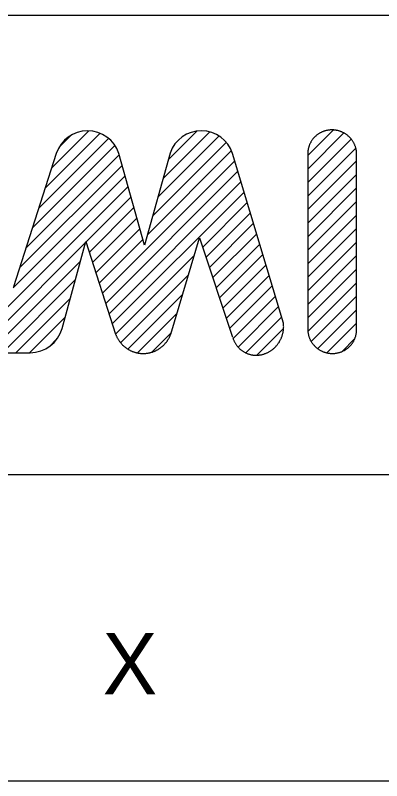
# Model space of a CAD drawing. Extents: x 563 to 1404, y 358 to 952.
# Drawn here: x 1199.82 to 1211.79, y 387.96 to 412.96 of the extents above; entities that cross this region are included whole.
import ezdxf

# ---------------------------------------------------------------- set-up
doc = ezdxf.new("R2010")
doc.units = 0
doc.layers.add('New Level (0)', color=7, linetype='Continuous')

# ---------------------------------------------------------------- blocks, each defined once
blk = doc.blocks.new('_U2')
at = {"layer": 'New Level (0)'}
for p, q in [((-3.034, 1.765), (-1.24, 3.56)), ((-2.825, 2.416), (-1.602, 3.64)), ((0.817, 2.081), (2.342, 3.605)), ((0.987, 2.693), (1.925, 3.631)), ((5.546, 2.833), (6.381, 3.668)), ((5.546, 2.391), (6.725, 3.57)), ((5.849, 3.507), (5.834, 3.495)), ((5.865, 3.518), (5.849, 3.507)), ((5.88, 3.529), (5.865, 3.518)), ((5.896, 3.54), (5.88, 3.529)), ((5.913, 3.55), (5.896, 3.54)), ((5.929, 3.56), (5.913, 3.55)), ((5.946, 3.57), (5.929, 3.56)), ((5.963, 3.579), (5.946, 3.57)), ((5.98, 3.587), (5.963, 3.579)), ((5.997, 3.596), (5.98, 3.587)), ((6.015, 3.603), (5.997, 3.596)), ((6.033, 3.611), (6.015, 3.603)), ((6.051, 3.618), (6.033, 3.611)), ((6.069, 3.624), (6.051, 3.618)), ((6.087, 3.631), (6.069, 3.624)), ((6.105, 3.636), (6.087, 3.631)), ((6.124, 3.642), (6.105, 3.636)), ((6.143, 3.646), (6.124, 3.642)), ((6.162, 3.651), (6.143, 3.646)), ((6.181, 3.655), (6.162, 3.651)), ((6.2, 3.658), (6.181, 3.655)), ((6.219, 3.661), (6.2, 3.658)), ((6.238, 3.664), (6.219, 3.661)), ((6.257, 3.666), (6.238, 3.664)), ((6.277, 3.667), (6.257, 3.666)), ((6.296, 3.668), (6.277, 3.667)), ((6.315, 3.669), (6.296, 3.668)), ((6.335, 3.669), (6.315, 3.669)), ((6.354, 3.669), (6.335, 3.669)), ((6.373, 3.668), (6.354, 3.669)), ((6.393, 3.667), (6.373, 3.668)), ((6.412, 3.666), (6.393, 3.667)), ((6.432, 3.664), (6.412, 3.666)), ((6.451, 3.661), (6.432, 3.664)), ((6.47, 3.658), (6.451, 3.661)), ((6.489, 3.655), (6.47, 3.658)), ((6.508, 3.651), (6.489, 3.655)), ((6.527, 3.646), (6.508, 3.651)), ((6.546, 3.641), (6.527, 3.646)), ((6.565, 3.636), (6.546, 3.641)), ((6.583, 3.631), (6.565, 3.636)), ((6.602, 3.624), (6.583, 3.631)), ((6.62, 3.618), (6.602, 3.624)), ((6.638, 3.611), (6.62, 3.618)), ((6.656, 3.603), (6.638, 3.611)), ((6.674, 3.596), (6.656, 3.603)), ((6.691, 3.587), (6.674, 3.596)), ((6.709, 3.579), (6.691, 3.587)), ((6.726, 3.57), (6.709, 3.579)), ((6.743, 3.56), (6.726, 3.57)), ((6.759, 3.55), (6.743, 3.56)), ((6.776, 3.54), (6.759, 3.55)), ((6.792, 3.529), (6.776, 3.54)), ((6.808, 3.518), (6.792, 3.529)), ((6.823, 3.507), (6.808, 3.518)), ((6.839, 3.495), (6.823, 3.507)), ((-3.244, 1.114), (-0.964, 3.394)), ((-2.578, 3.105), (-2.187, 3.496)), ((0.476, 0.856), (2.885, 3.265)), ((0.647, 1.468), (2.649, 3.471)), ((5.546, 1.949), (6.967, 3.369)), ((5.64, 3.263), (5.631, 3.246)), ((5.649, 3.28), (5.64, 3.263)), ((5.659, 3.296), (5.649, 3.28)), ((5.669, 3.312), (5.659, 3.296)), ((5.679, 3.328), (5.669, 3.312)), ((5.69, 3.343), (5.679, 3.328)), ((5.701, 3.359), (5.69, 3.343)), ((5.713, 3.374), (5.701, 3.359)), ((5.725, 3.389), (5.713, 3.374)), ((5.738, 3.403), (5.725, 3.389)), ((5.75, 3.417), (5.738, 3.403)), ((5.764, 3.431), (5.75, 3.417)), ((5.777, 3.444), (5.764, 3.431)), ((5.791, 3.458), (5.777, 3.444)), ((5.805, 3.47), (5.791, 3.458)), ((5.82, 3.483), (5.805, 3.47)), ((5.834, 3.495), (5.82, 3.483)), ((6.854, 3.483), (6.839, 3.495)), ((6.869, 3.47), (6.854, 3.483)), ((6.883, 3.457), (6.869, 3.47)), ((6.897, 3.444), (6.883, 3.457)), ((6.911, 3.431), (6.897, 3.444)), ((6.924, 3.417), (6.911, 3.431)), ((6.938, 3.403), (6.924, 3.417)), ((6.95, 3.388), (6.938, 3.403)), ((6.963, 3.374), (6.95, 3.388)), ((6.975, 3.359), (6.963, 3.374)), ((6.986, 3.343), (6.975, 3.359)), ((6.998, 3.328), (6.986, 3.343)), ((7.009, 3.312), (6.998, 3.328)), ((7.019, 3.296), (7.009, 3.312)), ((7.029, 3.28), (7.019, 3.296)), ((7.039, 3.263), (7.029, 3.28)), ((7.048, 3.246), (7.039, 3.263)), ((-3.453, 0.463), (-0.754, 3.161)), ((5.546, 1.507), (7.115, 3.076)), ((5.555, 3.013), (5.552, 2.994)), ((5.558, 3.032), (5.555, 3.013)), ((5.562, 3.05), (5.558, 3.032)), ((5.566, 3.069), (5.562, 3.05)), ((5.57, 3.087), (5.566, 3.069)), ((5.575, 3.105), (5.57, 3.087)), ((5.58, 3.124), (5.575, 3.105)), ((5.586, 3.142), (5.58, 3.124)), ((5.593, 3.159), (5.586, 3.142)), ((5.599, 3.177), (5.593, 3.159)), ((5.606, 3.195), (5.599, 3.177)), ((5.614, 3.212), (5.606, 3.195)), ((5.622, 3.229), (5.614, 3.212)), ((5.631, 3.246), (5.622, 3.229)), ((7.057, 3.229), (7.048, 3.246)), ((7.065, 3.212), (7.057, 3.229)), ((7.073, 3.195), (7.065, 3.212)), ((7.081, 3.177), (7.073, 3.195)), ((7.088, 3.159), (7.081, 3.177)), ((7.095, 3.141), (7.088, 3.159)), ((7.101, 3.123), (7.095, 3.141)), ((7.107, 3.105), (7.101, 3.123)), ((7.112, 3.087), (7.107, 3.105)), ((7.117, 3.069), (7.112, 3.087)), ((7.121, 3.05), (7.117, 3.069)), ((7.125, 3.031), (7.121, 3.05)), ((7.129, 3.013), (7.125, 3.031)), ((7.132, 2.994), (7.129, 3.013)), ((-2.669, 2.903), (-4.069, -1.454)), ((-3.662, -0.189), (-0.616, 2.857)), ((0.211, -0.097), (-0.629, 2.903)), ((1.048, 2.913), (0.211, -0.097)), ((0.306, 0.244), (3.056, 2.994)), ((4.75, -2.642), (3.091, 2.903)), ((5.547, 2.937), (5.546, 2.918)), ((5.546, 2.918), (5.546, 2.899)), ((5.546, 2.899), (5.546, 2.88)), ((5.546, 2.876), (5.546, -2.887)), ((5.548, 2.956), (5.547, 2.937)), ((5.55, 2.975), (5.548, 2.956)), ((5.552, 2.994), (5.55, 2.975)), ((7.135, 2.975), (7.132, 2.994)), ((7.137, 2.956), (7.135, 2.975)), ((7.138, 2.937), (7.137, 2.956)), ((7.139, 2.918), (7.138, 2.937)), ((7.139, -2.841), (7.139, 2.923)), ((-3.871, -0.84), (-0.52, 2.512)), ((-1.163, -1.667), (3.164, 2.66)), ((5.546, 1.065), (7.139, 2.658)), ((-1.056, -2.001), (3.266, 2.32)), ((-4.081, -1.492), (-0.423, 2.167)), ((5.546, 0.623), (7.139, 2.216)), ((-5.755, -3.607), (-0.326, 1.822)), ((-0.948, -2.336), (3.367, 1.98)), ((5.546, 0.181), (7.139, 1.774)), ((-0.84, -2.67), (3.469, 1.639)), ((-1.703, 0.003), (-0.23, 1.476)), ((2.112, -0.16), (3.571, 1.299)), ((5.546, -0.261), (7.139, 1.332)), ((-1.595, -0.331), (-0.133, 1.131)), ((-1.487, -0.665), (-0.036, 0.786)), ((2.222, -0.491), (3.673, 0.959)), ((5.546, -0.703), (7.139, 0.89)), ((2.333, -0.823), (3.774, 0.619)), ((-1.379, -0.999), (0.06, 0.44)), ((2.443, -1.154), (3.876, 0.279)), ((5.546, -1.145), (7.139, 0.448)), ((-2.482, -2.818), (-1.709, 0.023)), ((-1.709, 0.023), (-0.734, -2.997)), ((-1.271, -1.333), (0.157, 0.095)), ((1.072, -2.999), (2.011, 0.143)), ((2.011, 0.143), (3.091, -3.097)), ((5.546, -1.587), (7.139, 0.006)), ((-5.313, -3.607), (-1.719, -0.013)), ((2.554, -1.486), (3.978, -0.061)), ((-0.732, -3.004), (1.839, -0.433)), ((2.664, -1.817), (4.08, -0.402)), ((5.546, -2.028), (7.139, -0.436)), ((-4.871, -3.607), (-1.884, -0.62)), ((2.775, -2.149), (4.182, -0.742)), ((5.546, -2.47), (7.139, -0.878)), ((-4.429, -3.607), (-2.049, -1.227)), ((-0.569, -3.283), (1.651, -1.063)), ((2.885, -2.48), (4.283, -1.082)), ((2.996, -2.811), (4.385, -1.422)), ((5.548, -2.911), (7.139, -1.32)), ((-0.334, -3.49), (1.462, -1.694)), ((-3.987, -3.607), (-2.215, -1.835)), ((3.106, -3.143), (4.487, -1.762)), ((5.657, -3.243), (7.139, -1.762)), ((3.268, -3.423), (4.589, -2.102)), ((5.869, -3.474), (7.139, -2.204)), ((-3.545, -3.607), (-2.38, -2.442)), ((-0.018, -3.615), (1.273, -2.324)), ((3.52, -3.613), (4.691, -2.442)), ((4.749, -2.635), (4.746, -2.615)), ((4.752, -2.655), (4.749, -2.635)), ((4.754, -2.676), (4.752, -2.655)), ((4.756, -2.696), (4.754, -2.676)), ((4.757, -2.717), (4.756, -2.696)), ((4.757, -2.737), (4.757, -2.717)), ((4.758, -2.758), (4.757, -2.737)), ((6.172, -3.612), (7.139, -2.646)), ((0.447, -3.592), (1.085, -2.954)), ((3.886, -3.689), (4.755, -2.82)), ((4.724, -3.004), (4.73, -2.984)), ((4.73, -2.984), (4.734, -2.964)), ((4.734, -2.964), (4.739, -2.943)), ((4.739, -2.943), (4.743, -2.923)), ((4.743, -2.923), (4.746, -2.902)), ((4.746, -2.902), (4.749, -2.882)), ((4.749, -2.882), (4.752, -2.861)), ((4.752, -2.861), (4.754, -2.841)), ((4.754, -2.841), (4.755, -2.82)), ((4.755, -2.82), (4.757, -2.799)), ((4.757, -2.779), (4.758, -2.758)), ((4.757, -2.799), (4.757, -2.779)), ((5.546, -2.882), (5.547, -2.901)), ((5.547, -2.901), (5.549, -2.92)), ((5.549, -2.92), (5.551, -2.939)), ((5.551, -2.939), (5.554, -2.958)), ((5.554, -2.958), (5.557, -2.976)), ((5.557, -2.976), (5.56, -2.995)), ((5.56, -2.995), (5.564, -3.014)), ((7.124, -3.013), (7.128, -2.994)), ((7.128, -2.994), (7.131, -2.976)), ((7.131, -2.976), (7.133, -2.957)), ((7.133, -2.957), (7.136, -2.938)), ((7.136, -2.938), (7.137, -2.919)), ((7.137, -2.919), (7.138, -2.9)), ((7.138, -2.9), (7.139, -2.881)), ((7.139, -2.862), (7.139, -2.843)), ((7.139, -2.881), (7.139, -2.862)), ((-2.919, -3.423), (-2.627, -3.131)), ((-0.732, -3.003), (-0.725, -3.021)), ((-0.725, -3.021), (-0.718, -3.038)), ((-0.718, -3.038), (-0.711, -3.055)), ((-0.711, -3.055), (-0.703, -3.071)), ((-0.703, -3.071), (-0.695, -3.088)), ((-0.695, -3.088), (-0.687, -3.104)), ((-0.687, -3.104), (-0.678, -3.121)), ((-0.678, -3.121), (-0.67, -3.137)), ((-0.67, -3.137), (-0.66, -3.153)), ((-0.66, -3.153), (-0.651, -3.169)), ((-0.651, -3.169), (-0.641, -3.184)), ((-0.641, -3.184), (-0.631, -3.2)), ((-0.631, -3.2), (-0.621, -3.215)), ((-0.621, -3.215), (-0.61, -3.23)), ((-0.61, -3.23), (-0.6, -3.245)), ((-0.6, -3.245), (-0.588, -3.259)), ((0.925, -3.261), (0.937, -3.247)), ((0.937, -3.247), (0.947, -3.232)), ((0.947, -3.232), (0.958, -3.217)), ((0.958, -3.217), (0.968, -3.202)), ((0.968, -3.202), (0.978, -3.186)), ((0.978, -3.186), (0.988, -3.171)), ((0.988, -3.171), (0.998, -3.155)), ((0.998, -3.155), (1.007, -3.139)), ((1.007, -3.139), (1.016, -3.123)), ((1.016, -3.123), (1.024, -3.106)), ((1.024, -3.106), (1.032, -3.09)), ((1.032, -3.09), (1.04, -3.073)), ((1.04, -3.073), (1.048, -3.057)), ((1.048, -3.057), (1.055, -3.04)), ((1.055, -3.04), (1.063, -3.023)), ((1.063, -3.023), (1.069, -3.005)), ((3.1, -3.125), (3.106, -3.144)), ((3.106, -3.144), (3.113, -3.163)), ((3.113, -3.163), (3.12, -3.182)), ((3.12, -3.182), (3.128, -3.201)), ((3.128, -3.201), (3.136, -3.219)), ((3.136, -3.219), (3.145, -3.237)), ((3.145, -3.237), (3.154, -3.255)), ((4.617, -3.253), (4.627, -3.235)), ((4.627, -3.235), (4.638, -3.217)), ((4.638, -3.217), (4.648, -3.198)), ((4.648, -3.198), (4.657, -3.18)), ((4.657, -3.18), (4.666, -3.161)), ((4.666, -3.161), (4.675, -3.142)), ((4.675, -3.142), (4.683, -3.123)), ((4.683, -3.123), (4.691, -3.103)), ((4.691, -3.103), (4.699, -3.084)), ((4.699, -3.084), (4.706, -3.064)), ((4.706, -3.064), (4.712, -3.044)), ((4.712, -3.044), (4.719, -3.024)), ((4.719, -3.024), (4.724, -3.004)), ((5.564, -3.014), (5.569, -3.032)), ((5.569, -3.032), (5.574, -3.051)), ((5.574, -3.051), (5.579, -3.069)), ((5.579, -3.069), (5.585, -3.087)), ((5.585, -3.087), (5.591, -3.105)), ((5.591, -3.105), (5.598, -3.123)), ((5.598, -3.123), (5.605, -3.141)), ((5.605, -3.141), (5.613, -3.158)), ((5.613, -3.158), (5.621, -3.176)), ((5.621, -3.176), (5.629, -3.193)), ((5.629, -3.193), (5.638, -3.21)), ((5.638, -3.21), (5.647, -3.227)), ((5.647, -3.227), (5.657, -3.243)), ((5.657, -3.243), (5.667, -3.259)), ((6.653, -3.574), (7.086, -3.141)), ((7.027, -3.259), (7.037, -3.242)), ((7.037, -3.242), (7.046, -3.226)), ((7.046, -3.226), (7.055, -3.209)), ((7.055, -3.209), (7.064, -3.192)), ((7.064, -3.192), (7.072, -3.175)), ((7.072, -3.175), (7.079, -3.158)), ((7.079, -3.158), (7.086, -3.14)), ((7.086, -3.14), (7.093, -3.122)), ((7.093, -3.122), (7.099, -3.104)), ((7.099, -3.104), (7.105, -3.086)), ((7.105, -3.086), (7.111, -3.068)), ((7.111, -3.068), (7.116, -3.05)), ((7.116, -3.05), (7.12, -3.031)), ((7.12, -3.031), (7.124, -3.013)), ((-0.588, -3.259), (-0.577, -3.274)), ((-0.577, -3.274), (-0.565, -3.288)), ((-0.565, -3.288), (-0.554, -3.302)), ((-0.554, -3.302), (-0.541, -3.316)), ((-0.541, -3.316), (-0.529, -3.329)), ((-0.529, -3.329), (-0.516, -3.343)), ((-0.516, -3.343), (-0.503, -3.356)), ((-0.503, -3.356), (-0.49, -3.368)), ((-0.49, -3.368), (-0.477, -3.381)), ((-0.477, -3.381), (-0.463, -3.393)), ((-0.463, -3.393), (-0.45, -3.405)), ((-0.45, -3.405), (-0.436, -3.417)), ((-0.436, -3.417), (-0.421, -3.428)), ((-0.421, -3.428), (-0.407, -3.439)), ((-0.407, -3.439), (-0.392, -3.45)), ((-0.392, -3.45), (-0.377, -3.461)), ((-0.377, -3.461), (-0.362, -3.471)), ((-0.362, -3.471), (-0.347, -3.481)), ((-0.347, -3.481), (-0.332, -3.491)), ((-0.332, -3.491), (-0.316, -3.501)), ((0.653, -3.502), (0.668, -3.492)), ((0.668, -3.492), (0.684, -3.483)), ((0.684, -3.483), (0.699, -3.473)), ((0.699, -3.473), (0.714, -3.462)), ((0.714, -3.462), (0.729, -3.452)), ((0.729, -3.452), (0.743, -3.441)), ((0.743, -3.441), (0.758, -3.43)), ((0.758, -3.43), (0.772, -3.418)), ((0.772, -3.418), (0.786, -3.407)), ((0.786, -3.407), (0.8, -3.395)), ((0.8, -3.395), (0.814, -3.382)), ((0.814, -3.382), (0.827, -3.37)), ((0.827, -3.37), (0.84, -3.357)), ((0.84, -3.357), (0.853, -3.344)), ((0.853, -3.344), (0.866, -3.331)), ((0.866, -3.331), (0.878, -3.317)), ((0.878, -3.317), (0.89, -3.304)), ((0.89, -3.304), (0.902, -3.29)), ((0.902, -3.29), (0.914, -3.276)), ((0.914, -3.276), (0.925, -3.261)), ((3.154, -3.255), (3.163, -3.273)), ((3.163, -3.273), (3.173, -3.29)), ((3.173, -3.29), (3.183, -3.307)), ((3.183, -3.307), (3.194, -3.324)), ((3.194, -3.324), (3.205, -3.341)), ((3.205, -3.341), (3.216, -3.357)), ((3.216, -3.357), (3.228, -3.373)), ((3.228, -3.373), (3.24, -3.389)), ((3.24, -3.389), (3.252, -3.404)), ((3.252, -3.404), (3.265, -3.419)), ((3.265, -3.419), (3.278, -3.434)), ((3.278, -3.434), (3.292, -3.448)), ((3.292, -3.448), (3.306, -3.462)), ((3.306, -3.462), (3.32, -3.476)), ((3.32, -3.476), (3.334, -3.489)), ((3.334, -3.489), (3.349, -3.502)), ((4.397, -3.5), (4.413, -3.487)), ((4.413, -3.487), (4.429, -3.474)), ((4.429, -3.474), (4.444, -3.46)), ((4.444, -3.46), (4.46, -3.446)), ((4.46, -3.446), (4.475, -3.432)), ((4.475, -3.432), (4.489, -3.417)), ((4.489, -3.417), (4.503, -3.402)), ((4.503, -3.402), (4.517, -3.387)), ((4.517, -3.387), (4.531, -3.371)), ((4.531, -3.371), (4.544, -3.355)), ((4.544, -3.355), (4.557, -3.339)), ((4.557, -3.339), (4.57, -3.322)), ((4.57, -3.322), (4.582, -3.305)), ((4.582, -3.305), (4.594, -3.288)), ((4.594, -3.288), (4.606, -3.271)), ((4.606, -3.271), (4.617, -3.253)), ((5.667, -3.259), (5.678, -3.275)), ((5.678, -3.275), (5.688, -3.291)), ((5.688, -3.291), (5.7, -3.307)), ((5.7, -3.307), (5.711, -3.322)), ((5.711, -3.322), (5.723, -3.337)), ((5.723, -3.337), (5.736, -3.352)), ((5.736, -3.352), (5.749, -3.366)), ((5.749, -3.366), (5.762, -3.38)), ((5.762, -3.38), (5.775, -3.394)), ((5.775, -3.394), (5.789, -3.408)), ((5.789, -3.408), (5.803, -3.421)), ((5.803, -3.421), (5.818, -3.434)), ((5.818, -3.434), (5.832, -3.446)), ((5.832, -3.446), (5.847, -3.458)), ((5.847, -3.458), (5.863, -3.47)), ((5.863, -3.47), (5.878, -3.481)), ((5.878, -3.481), (5.894, -3.493)), ((5.894, -3.493), (5.91, -3.503)), ((6.789, -3.503), (6.805, -3.492)), ((6.805, -3.492), (6.821, -3.481)), ((6.821, -3.481), (6.836, -3.47)), ((6.836, -3.47), (6.851, -3.458)), ((6.851, -3.458), (6.866, -3.446)), ((6.866, -3.446), (6.881, -3.433)), ((6.881, -3.433), (6.895, -3.42)), ((6.895, -3.42), (6.909, -3.407)), ((6.909, -3.407), (6.922, -3.394)), ((6.922, -3.394), (6.935, -3.38)), ((6.935, -3.38), (6.948, -3.366)), ((6.948, -3.366), (6.961, -3.351)), ((6.961, -3.351), (6.973, -3.336)), ((6.973, -3.336), (6.984, -3.321)), ((6.984, -3.321), (6.996, -3.306)), ((6.996, -3.306), (7.007, -3.291)), ((7.007, -3.291), (7.017, -3.275)), ((7.017, -3.275), (7.027, -3.259)), ((-6.792, -3.607), (-3.523, -3.607)), ((-0.316, -3.501), (-0.3, -3.51)), ((-0.3, -3.51), (-0.284, -3.519)), ((-0.284, -3.519), (-0.268, -3.527)), ((-0.268, -3.527), (-0.252, -3.535)), ((-0.252, -3.535), (-0.236, -3.543)), ((-0.236, -3.543), (-0.219, -3.551)), ((-0.219, -3.551), (-0.203, -3.558)), ((-0.203, -3.558), (-0.186, -3.565)), ((-0.186, -3.565), (-0.169, -3.572)), ((-0.169, -3.572), (-0.152, -3.578)), ((-0.152, -3.578), (-0.135, -3.584)), ((-0.135, -3.584), (-0.117, -3.59)), ((-0.117, -3.59), (-0.1, -3.595)), ((-0.1, -3.595), (-0.083, -3.6)), ((-0.083, -3.6), (-0.065, -3.605)), ((-0.065, -3.605), (-0.048, -3.609)), ((-0.048, -3.609), (-0.03, -3.613)), ((-0.03, -3.613), (-0.012, -3.617)), ((-0.012, -3.617), (0.006, -3.62)), ((0.006, -3.62), (0.024, -3.623)), ((0.024, -3.623), (0.042, -3.625)), ((0.042, -3.625), (0.06, -3.628)), ((0.06, -3.628), (0.078, -3.63)), ((0.078, -3.63), (0.096, -3.631)), ((0.096, -3.631), (0.114, -3.632)), ((0.114, -3.632), (0.132, -3.633)), ((0.132, -3.633), (0.15, -3.634)), ((0.15, -3.634), (0.168, -3.634)), ((0.168, -3.634), (0.186, -3.634)), ((0.186, -3.634), (0.204, -3.633)), ((0.204, -3.633), (0.222, -3.633)), ((0.222, -3.633), (0.24, -3.631)), ((0.24, -3.631), (0.259, -3.63)), ((0.259, -3.63), (0.277, -3.628)), ((0.277, -3.628), (0.295, -3.626)), ((0.295, -3.626), (0.312, -3.623)), ((0.312, -3.623), (0.33, -3.62)), ((0.33, -3.62), (0.348, -3.617)), ((0.348, -3.617), (0.366, -3.613)), ((0.366, -3.613), (0.384, -3.609)), ((0.384, -3.609), (0.401, -3.605)), ((0.401, -3.605), (0.419, -3.601)), ((0.419, -3.601), (0.436, -3.595)), ((0.436, -3.595), (0.454, -3.59)), ((0.454, -3.59), (0.471, -3.585)), ((0.471, -3.585), (0.488, -3.579)), ((0.488, -3.579), (0.505, -3.572)), ((0.505, -3.572), (0.522, -3.566)), ((0.522, -3.566), (0.539, -3.559)), ((0.539, -3.559), (0.556, -3.552)), ((0.556, -3.552), (0.572, -3.544)), ((0.572, -3.544), (0.589, -3.536)), ((0.589, -3.536), (0.605, -3.528)), ((0.605, -3.528), (0.621, -3.519)), ((0.621, -3.519), (0.637, -3.511)), ((0.637, -3.511), (0.653, -3.502)), ((3.349, -3.502), (3.364, -3.514)), ((3.364, -3.514), (3.38, -3.527)), ((3.38, -3.527), (3.396, -3.538)), ((3.396, -3.538), (3.411, -3.55)), ((3.411, -3.55), (3.428, -3.561)), ((3.428, -3.561), (3.444, -3.571)), ((3.444, -3.571), (3.461, -3.581)), ((3.461, -3.581), (3.478, -3.591)), ((3.478, -3.591), (3.495, -3.6)), ((3.495, -3.6), (3.513, -3.609)), ((3.513, -3.609), (3.53, -3.617)), ((3.53, -3.617), (3.548, -3.625)), ((3.548, -3.625), (3.566, -3.633)), ((3.566, -3.633), (3.585, -3.64)), ((3.585, -3.64), (3.603, -3.647)), ((3.603, -3.647), (3.622, -3.653)), ((3.622, -3.653), (3.64, -3.658)), ((3.64, -3.658), (3.659, -3.664)), ((3.659, -3.664), (3.678, -3.668)), ((3.678, -3.668), (3.698, -3.673)), ((3.698, -3.673), (3.717, -3.676)), ((3.717, -3.676), (3.736, -3.68)), ((3.736, -3.68), (3.756, -3.683)), ((3.756, -3.683), (3.775, -3.685)), ((3.775, -3.685), (3.795, -3.687)), ((3.795, -3.687), (3.815, -3.688)), ((3.815, -3.688), (3.834, -3.689)), ((3.834, -3.689), (3.854, -3.69)), ((3.854, -3.69), (3.874, -3.69)), ((3.874, -3.69), (3.894, -3.689)), ((3.894, -3.689), (3.913, -3.688)), ((3.913, -3.688), (3.933, -3.687)), ((3.933, -3.687), (3.953, -3.685)), ((3.953, -3.685), (3.973, -3.682)), ((3.973, -3.682), (3.993, -3.679)), ((3.993, -3.679), (4.012, -3.676)), ((4.012, -3.676), (4.032, -3.672)), ((4.032, -3.672), (4.052, -3.668)), ((4.052, -3.668), (4.071, -3.663)), ((4.071, -3.663), (4.091, -3.658)), ((4.091, -3.658), (4.11, -3.652)), ((4.11, -3.652), (4.129, -3.646)), ((4.129, -3.646), (4.148, -3.639)), ((4.148, -3.639), (4.167, -3.632)), ((4.167, -3.632), (4.186, -3.624)), ((4.186, -3.624), (4.205, -3.616)), ((4.205, -3.616), (4.223, -3.608)), ((4.223, -3.608), (4.241, -3.599)), ((4.241, -3.599), (4.26, -3.59)), ((4.26, -3.59), (4.277, -3.58)), ((4.277, -3.58), (4.295, -3.57)), ((4.295, -3.57), (4.313, -3.559)), ((4.313, -3.559), (4.33, -3.548)), ((4.33, -3.548), (4.347, -3.537)), ((4.347, -3.537), (4.364, -3.525)), ((4.364, -3.525), (4.381, -3.513)), ((4.381, -3.513), (4.397, -3.5)), ((5.91, -3.503), (5.927, -3.513)), ((5.927, -3.513), (5.944, -3.523)), ((5.944, -3.523), (5.96, -3.533)), ((5.96, -3.533), (5.978, -3.542)), ((5.978, -3.542), (5.995, -3.551)), ((5.995, -3.551), (6.013, -3.559)), ((6.013, -3.559), (6.03, -3.567)), ((6.03, -3.567), (6.048, -3.574)), ((6.048, -3.574), (6.066, -3.581)), ((6.066, -3.581), (6.085, -3.587)), ((6.085, -3.587), (6.103, -3.594)), ((6.103, -3.594), (6.122, -3.599)), ((6.122, -3.599), (6.14, -3.605)), ((6.14, -3.605), (6.159, -3.609)), ((6.159, -3.609), (6.178, -3.614)), ((6.178, -3.614), (6.197, -3.618)), ((6.197, -3.618), (6.216, -3.621)), ((6.216, -3.621), (6.235, -3.624)), ((6.235, -3.624), (6.255, -3.627)), ((6.255, -3.627), (6.274, -3.629)), ((6.274, -3.629), (6.293, -3.63)), ((6.293, -3.63), (6.313, -3.631)), ((6.313, -3.631), (6.332, -3.632)), ((6.332, -3.632), (6.351, -3.632)), ((6.351, -3.632), (6.371, -3.632)), ((6.371, -3.632), (6.39, -3.631)), ((6.39, -3.631), (6.41, -3.63)), ((6.41, -3.63), (6.429, -3.629)), ((6.429, -3.629), (6.448, -3.626)), ((6.448, -3.626), (6.467, -3.624)), ((6.467, -3.624), (6.486, -3.621)), ((6.486, -3.621), (6.506, -3.617)), ((6.506, -3.617), (6.524, -3.613)), ((6.524, -3.613), (6.543, -3.609)), ((6.543, -3.609), (6.562, -3.604)), ((6.562, -3.604), (6.581, -3.599)), ((6.581, -3.599), (6.599, -3.593)), ((6.599, -3.593), (6.617, -3.587)), ((6.617, -3.587), (6.635, -3.581)), ((6.635, -3.581), (6.653, -3.574)), ((6.653, -3.574), (6.671, -3.566)), ((6.671, -3.566), (6.689, -3.558)), ((6.689, -3.558), (6.706, -3.55)), ((6.706, -3.55), (6.723, -3.541)), ((6.723, -3.541), (6.74, -3.532)), ((6.74, -3.532), (6.757, -3.523)), ((6.757, -3.523), (6.773, -3.513)), ((6.773, -3.513), (6.789, -3.503))]:
    blk.add_line(p, q, dxfattribs=at)
for centre, radius, start, end in [((-1.649, 2.567), 1.074, 18.2263, 161.7737), ((2.068, 2.562), 1.078, 18.3932, 161.0321), ((-3.523, -2.527), 1.08, 270, 344.3963)]:
    blk.add_arc(centre, radius, start, end, dxfattribs=at)

msp = doc.modelspace()

# ---------------------------------------------------------------- linework, layer by layer
at = {"layer": 'New Level (0)'}
for p, q in [((572.577, 412.956), (1393.577, 412.956)), ((1143.577, 397.956), (1325.577, 397.956)), ((1143.577, 387.956), (1223.577, 387.956))]:
    msp.add_line(p, q, dxfattribs=at)

# ---------------------------------------------------------------- block references
msp.add_blockref('_U2', (1203.825, 405.543), dxfattribs=at)

# ---------------------------------------------------------------- texts
msp.add_text('X', height=2, dxfattribs=at).set_placement((1202.669, 390.775))

doc.saveas('drawing.dxf')
